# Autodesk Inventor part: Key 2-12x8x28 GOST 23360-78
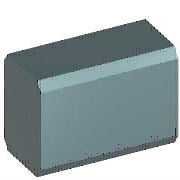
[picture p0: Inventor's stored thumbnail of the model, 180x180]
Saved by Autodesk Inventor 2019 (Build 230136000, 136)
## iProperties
Created: 2018-01
Part Number: Key 2-12x8x28 GOST 23360-78
Material: Steel, Mild
Description: Keyed joints with sunk keys
Document SubType Name: Modeling
Standard: GOST 23360-78 (2)
Designer: m.vorobev
Standards Organization: GOST
Language: en-US
Size Designation: 12 x 8 x 28
Categories: <MemberInstance><Categories><Category DisplayName="Shaft Parts" InternalName="7f7aeb1f-a693-4053-b835-cee3144e0d98" Mnemonic="SHFT"><Category DisplayName="Keys"
Density: 7.85 g/cm^3
Appearance: Semi-Polished
IsCustomPart: 1
Author: m.vorobev
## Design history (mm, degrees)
sketch "Sketch1"
  geometry: L1 (6, 6)-(32, 6); L2 (32, 6)-(32, -6); L3 (32, -6)-(6, -6); L4 (0, 8.4)-(0, -8.4) reference; L5 (-6.4, 0)-(38.4, 0) reference; L6 (6, 6)-(6, -6); A1 r 6 centre (6, 0) between (6, 6) and (6, -6)
  constraints: 8 end point, 3 tangent, 2 perpendicular, 2 point on circle, 1 centre point, 1 horizontal, 1 parallel, 1 point on line
  dimensions: "d0" = 6 radius of A1 (= 0.5 x PB); "d19" = 26 distance of L1.start L1.end
extrude "Body1" new body sketch "Sketch1" taper "d3" = 0 deg; stored distance "d4" = 10
body "Solid1"
workplane "Work Plane1"
workplane "Work Plane2"
chamfer "Chamfer1" distance "d8" = 0.4 (= PHH); stored, may be unused: second distance "d9" = 0.4 (= PHH), angle "d13" = 45 deg
other parameters: "d1" = -5 (= -PNT), "d2" = 3 (= PH - PNT), "NLG" = 28 [user parameter], "PB" = 12 [user parameter; used in 1 equation term], "PNT" = 5 [user parameter; used in 2 equation terms], "PH" = 8 [user parameter; used in 1 equation term], "PHH" = 0.4 [user parameter; used in 2 equation terms], "d10" = 0, "d16" = 0, "d17" = 0, "d18" = 0, "RR" = 0.25 [user parameter], "WDMIN" = 38 [user parameter], "WDMAX" = 44 [user parameter], "PLB1" = 34 [user parameter], "PUEB" = 3.3 [user parameter]
